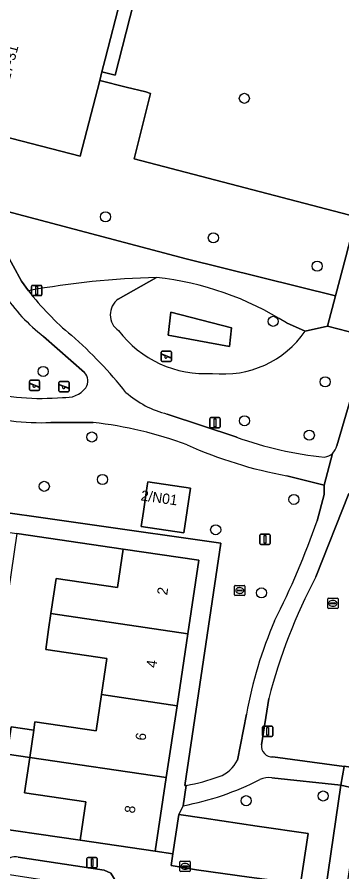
# Model space of a CAD drawing. Extents: x 163683 to 164494, y 382709 to 383872.
# Drawn here: x 164137.6 to 164169, y 383039.4 to 383122.3 of the extents above; entities that cross this region are included whole.
import ezdxf

# ---------------------------------------------------------------- set-up
doc = ezdxf.new("R2010")
doc.units = 0
for name, color, linetype in [('IMGEO_Boom', 7, 'Continuous'), ('IMGEO_Erf', 7, 'Continuous'), ('IMGEO_Groenvoorziening', 7, 'Continuous'), ('IMGEO_Kolk', 7, 'Continuous'), ('IMGEO_Lichtmast', 7, 'Continuous'), ('IMGEO_Pand', 7, 'Continuous'), ('IMGEO_Pand_nummerreeks', 7, 'Continuous'), ('IMGEO_Parkeervlak_open', 7, 'Continuous'), ('IMGEO_Rioolput', 7, 'Continuous'), ('IMGEO_Speelvoorziening', 7, 'Continuous'), ('IMGEO_Voetpad_halfverhard', 7, 'Continuous'), ('IMGEO_Voetpad_open', 7, 'Continuous')]:
    doc.layers.add(name, color=color, linetype=linetype)

msp = doc.modelspace()

# ---------------------------------------------------------------- linework, layer by layer
at = {"layer": 'IMGEO_Boom'}
for centre in [(164159.549, 383114.408), (164146.112, 383102.917), (164156.55, 383100.879), (164166.599, 383098.137), (164162.334, 383092.784), (164140.074, 383087.929), (164167.374, 383086.924), (164159.567, 383083.143), (164144.782, 383081.568), (164165.84, 383081.743), (164145.822, 383077.443), (164140.182, 383076.784), (164164.349, 383075.518), (164156.775, 383072.577), (164161.207, 383066.45), (164159.731, 383046.3), (164167.183, 383046.756)]:
    msp.add_circle(centre, 0.489, dxfattribs=at)
at = {"layer": 'IMGEO_Erf'}
msp.add_lwpolyline([(164146.251, 383060.095), (164140.317, 383060.973), (164140.602, 383062.903), (164140.829, 383064.44), (164141.333, 383067.849), (164147.268, 383066.971), (164147.817, 383070.691), (164137.509, 383072.212), (164133.407, 383043.974), (164143.649, 383042.486), (164144.194, 383046.176), (164138.26, 383047.054), (164138.767, 383050.485), (164136.597, 383050.805), (164136.989, 383053.462), (164139.16, 383053.142), (164139.279, 383053.95), (164145.213, 383053.072), (164145.733, 383056.587)], close=True, dxfattribs=at)
at = {"layer": 'IMGEO_Groenvoorziening'}
for points in [[(164176.537, 383126.569), (164154.315, 383132.306), (164153.975, 383138.872), (164152.776, 383139.237), (164150.9, 383131.848), (164147.04, 383116.646), (164145.764, 383116.973), (164145.551, 383116.143), (164148.108, 383115.477), (164150.025, 383115.042), (164150.47, 383114.883), (164148.895, 383108.547), (164170.385, 383102.927)], [(164130.601, 383105.021), (164153.924, 383098.841), (164168.382, 383095.258), (164169.377, 383099.053), (164170.385, 383102.927), (164148.895, 383108.547), (164150.47, 383114.883), (164150.025, 383115.042), (164148.108, 383115.477), (164145.551, 383116.143), (164143.667, 383108.811), (164132.278, 383111.736)], [(164158.309, 383092.167), (164152.448, 383093.678), (164152.161, 383091.446), (164158.123, 383090.334)], [(164158.123, 383090.334), (164152.161, 383091.446), (164152.448, 383093.678), (164158.309, 383092.167)], [(164149.789, 383074.346), (164150.153, 383076.819), (164150.211, 383077.209), (164154.321, 383076.602), (164153.683, 383072.277), (164149.573, 383072.884)]]:
    msp.add_lwpolyline(points, close=True, dxfattribs=at)
for points in [[(164163.632, 383092.626), (164165.451, 383091.845), (164167.61, 383092.316), (164168.382, 383095.258), (164153.924, 383098.841), (164130.601, 383105.021), (164130.639, 383104.838), (164133.407, 383104.018)], [(164135.521, 383101.151), (164137.968, 383096.684), (164138.654, 383095.757)], [(164151.054, 383097.04), (164147.334, 383094.937)], [(164147.334, 383094.937), (164151.054, 383097.04)], [(164165.451, 383091.845), (164163.632, 383092.626)], [(164168.497, 383080.71), (164171.615, 383091.268), (164167.61, 383092.316), (164165.451, 383091.845)], [(164144.086, 383087.825), (164140.116, 383091.323)], [(164152.091, 383083.795), (164158.807, 383081.554)], [(164144.917, 383082.973), (164140.824, 383082.983)], [(164132.4, 383077.957), (164131.864, 383074.9), (164157.283, 383071.277), (164153.793, 383047.768), (164153.917, 383047.788)], [(164167.263, 383076.913), (164163.67, 383077.798)], [(164166.586, 383073.45), (164167.273, 383076.003), (164167.263, 383076.913)], [(164169.676, 383076.099), (164166.477, 383067.998)], [(164161.918, 383056.219), (164161.209, 383051.719)], [(164158.873, 383050.234), (164159.754, 383054.687)], [(164162.319, 383050.556), (164169.216, 383049.609), (164169.223, 383049.653), (164170.675, 383049.429), (164171.064, 383051.879), (164171.559, 383055)], [(164153.629, 383045.816), (164153.2, 383044.955), (164155.662, 383044.603), (164160.791, 383043.822), (164165.739, 383043.108), (164164.98, 383038.234), (164167.449, 383037.807), (164168.897, 383047.801), (164162.226, 383048.525)]]:
    msp.add_lwpolyline(points, dxfattribs=at)
for centre, radius, start, end in [((164153.179, 383015.942), 81.126, 91.50073, 100.31376), ((164153.179, 383015.942), 81.126, 91.50073, 100.31376), ((164147.804, 383067.65), 29.57, 57.63606, 83.68891), ((164147.804, 383067.65), 29.57, 57.63606, 83.68891), ((164159.128, 383111.286), 25.697, 217.1799, 230.57615), ((164150.163, 383104.484), 16.558, 212.9844, 232.6429), ((164148.439, 383093.423), 1.874, 126.13062, 235.10876), ((164148.439, 383093.423), 1.874, 126.13062, 235.10876), ((164155.738, 383098.19), 10.48, 216.98172, 273.91583), ((164155.738, 383098.19), 10.48, 216.98172, 273.91583), ((164157.528, 383097.287), 9.612, 263.58564, 325.518), ((164157.528, 383097.287), 9.612, 263.58564, 325.518), ((164114.666, 383059.327), 42.697, 38.48096, 48.76649), ((164143.179, 383087), 1.227, 327.06643, 42.28285), ((164139.889, 383108.442), 23.13, 255.39685, 275.11791), ((164142.228, 383087.939), 2.55, 263.79675, 320.96607), ((164154.385, 383093.027), 9.513, 228.56764, 256.0452), ((164139.731, 383105.192), 22.236, 253.05037, 272.81875), ((164140.661, 383044.977), 38.234, 69.56721, 83.60918), ((164171.601, 383120.302), 43.238, 245.9918, 259.43054), ((164170.806, 383114.682), 35.235, 250.08908, 264.31636), ((164167.139, 383080.996), 1.386, 277.38337, 312.76546), ((164167.13, 383081.004), 1.399, 312.80443, 347.85765), ((164092.514, 383099.049), 78.371, 333.21214, 340.9352), ((164213.759, 383042.926), 53.518, 152.06448, 165.61819), ((164200.877, 383047.245), 41.791, 156.77014, 169.74186), ((164162.233, 383051.585), 1.033, 172.54823, 274.7803), ((164156.069, 383051.569), 3.106, 289.52971, 334.53785), ((164150.848, 383065.636), 18.11, 279.75605, 290.21855), ((164162.012, 383045.902), 2.632, 85.34553, 111.59273), ((164148.762, 383072.184), 26.814, 280.45862, 297.26222)]:
    msp.add_arc(centre, radius, start, end, dxfattribs=at)
at = {"layer": 'IMGEO_Kolk'}
for p, q in [((164153.312, 383039.503), (164153.312, 383040.355)), ((164153.387, 383040.429), (164154.239, 383040.429)), ((164153.8, 383040.209), (164153.825, 383040.209)), ((164154.313, 383040.355), (164154.313, 383039.503)), ((164154.239, 383039.429), (164153.387, 383039.429)), ((164153.571, 383039.923), (164153.571, 383039.935)), ((164154.009, 383039.886), (164153.611, 383039.886)), ((164153.614, 383039.972), (164154.012, 383039.972)), ((164153.823, 383039.649), (164153.798, 383039.649)), ((164154.055, 383039.935), (164154.055, 383039.923))]:
    msp.add_line(p, q, dxfattribs=at)
for points in [[(164153.312, 383039.503), (164153.312, 383040.355)], [(164153.387, 383040.429), (164154.239, 383040.429)], [(164154.313, 383040.355), (164154.313, 383039.503)], [(164154.239, 383039.429), (164153.387, 383039.429)]]:
    msp.add_lwpolyline(points, dxfattribs=at)
for centre, radius, start, end in [((164153.389, 383040.353), 0.0765, 91.55205, 178.44795), ((164153.389, 383040.353), 0.0765, 91.55205, 178.44795), ((164154.237, 383040.353), 0.0765, 1.55205, 88.44795), ((164154.237, 383040.353), 0.0765, 1.55205, 88.44795), ((164153.389, 383039.505), 0.0765, 181.55205, 268.44795), ((164153.389, 383039.505), 0.0765, 181.55205, 268.44795), ((164153.611, 383039.932), 0.0403, 85.87752, 175.75265), ((164153.608, 383039.922), 0.0366, 178.93798, 274.71019), ((164154.012, 383039.929), 0.043, 264.86636, 352.45326), ((164154.016, 383039.934), 0.0386, 1.73085, 96.63898), ((164154.237, 383039.505), 0.0765, 271.55205, 358.44795), ((164154.237, 383039.505), 0.0765, 271.55205, 358.44795)]:
    msp.add_arc(centre, radius, start, end, dxfattribs=at)
for centre, major_axis, ratio, start_param, end_param in [((164153.799, 383039.929), (-0.387, 0.002), 0.722429, 4.712389, 7.853982), ((164153.824, 383039.929), (-0.39, 0.002), 0.717154, 1.570796, 4.712389)]:
    msp.add_ellipse(centre, major_axis=major_axis, ratio=ratio, start_param=start_param, end_param=end_param, dxfattribs=at)
at = {"layer": 'IMGEO_Lichtmast'}
for p, q in [((164138.958, 383095.375), (164138.958, 383096.175)), ((164138.958, 383096.175), (164138.958, 383095.375)), ((164139.058, 383096.275), (164139.848, 383096.275)), ((164139.848, 383096.275), (164139.058, 383096.275)), ((164139.948, 383096.175), (164139.948, 383095.375)), ((164139.948, 383095.375), (164139.948, 383096.175)), ((164139.848, 383095.275), (164139.058, 383095.275)), ((164139.058, 383095.275), (164139.848, 383095.275)), ((164156.212, 383082.545), (164156.212, 383083.345)), ((164156.212, 383083.345), (164156.212, 383082.545)), ((164156.312, 383083.445), (164157.102, 383083.445)), ((164157.102, 383083.445), (164156.312, 383083.445)), ((164157.202, 383083.345), (164157.202, 383082.545)), ((164157.202, 383082.545), (164157.202, 383083.345)), ((164157.102, 383082.445), (164156.312, 383082.445)), ((164156.312, 383082.445), (164157.102, 383082.445)), ((164161.051, 383071.246), (164161.051, 383072.046)), ((164161.051, 383072.046), (164161.051, 383071.246)), ((164161.151, 383072.146), (164161.941, 383072.146)), ((164161.941, 383072.146), (164161.151, 383072.146)), ((164162.041, 383072.046), (164162.041, 383071.246)), ((164162.041, 383071.246), (164162.041, 383072.046)), ((164161.941, 383071.146), (164161.151, 383071.146)), ((164161.151, 383071.146), (164161.941, 383071.146)), ((164161.307, 383052.633), (164161.307, 383053.433)), ((164161.307, 383053.433), (164161.307, 383052.633)), ((164161.407, 383053.533), (164162.197, 383053.533)), ((164162.197, 383053.533), (164161.407, 383053.533)), ((164162.297, 383053.433), (164162.297, 383052.633)), ((164162.297, 383052.633), (164162.297, 383053.433)), ((164162.197, 383052.533), (164161.407, 383052.533)), ((164161.407, 383052.533), (164162.197, 383052.533)), ((164144.316, 383039.879), (164144.316, 383040.679)), ((164144.316, 383040.679), (164144.316, 383039.879)), ((164144.416, 383040.779), (164145.206, 383040.779)), ((164145.206, 383040.779), (164144.416, 383040.779)), ((164145.306, 383040.679), (164145.306, 383039.879)), ((164145.306, 383039.879), (164145.306, 383040.679)), ((164145.206, 383039.779), (164144.416, 383039.779)), ((164144.416, 383039.779), (164145.206, 383039.779))]:
    msp.add_line(p, q, dxfattribs=at)
for points in [[(164139.378, 383096.15), (164139.528, 383096.15), (164139.528, 383095.4), (164139.378, 383095.4), (164139.378, 383096.15)], [(164156.632, 383083.32), (164156.782, 383083.32), (164156.782, 383082.57), (164156.632, 383082.57), (164156.632, 383083.32)], [(164161.471, 383072.021), (164161.621, 383072.021), (164161.621, 383071.271), (164161.471, 383071.271), (164161.471, 383072.021)], [(164161.727, 383053.408), (164161.877, 383053.408), (164161.877, 383052.658), (164161.727, 383052.658), (164161.727, 383053.408)], [(164144.736, 383040.654), (164144.886, 383040.654), (164144.886, 383039.904), (164144.736, 383039.904), (164144.736, 383040.654)]]:
    msp.add_lwpolyline(points, dxfattribs=at)
for centre, start, end in [((164139.058, 383096.175), 90, 180), ((164139.058, 383096.175), 90, 180), ((164139.848, 383096.175), 0, 90), ((164139.848, 383096.175), 360, 90), ((164139.058, 383095.375), 180, 270), ((164139.058, 383095.375), 180, 270), ((164139.848, 383095.375), 270, 0), ((164139.848, 383095.375), 270, 0), ((164156.312, 383083.345), 90, 180), ((164156.312, 383083.345), 90, 180), ((164157.102, 383083.345), 0, 90), ((164157.102, 383083.345), 360, 90), ((164156.312, 383082.545), 180, 270), ((164156.312, 383082.545), 180, 270), ((164157.102, 383082.545), 270, 0), ((164157.102, 383082.545), 270, 0), ((164161.151, 383072.046), 90, 180), ((164161.151, 383072.046), 90, 180), ((164161.941, 383072.046), 0, 90), ((164161.941, 383072.046), 360, 90), ((164161.151, 383071.246), 180, 270), ((164161.151, 383071.246), 180, 270), ((164161.941, 383071.246), 270, 0), ((164161.941, 383071.246), 270, 0), ((164161.407, 383053.433), 90, 180), ((164161.407, 383053.433), 90, 180), ((164162.197, 383053.433), 0, 90), ((164162.197, 383053.433), 360, 90), ((164161.407, 383052.633), 180, 270), ((164161.407, 383052.633), 180, 270), ((164162.197, 383052.633), 270, 0), ((164162.197, 383052.633), 270, 0), ((164144.416, 383040.679), 90, 180), ((164144.416, 383040.679), 90, 180), ((164145.206, 383040.679), 0, 90), ((164145.206, 383040.679), 360, 90), ((164144.416, 383039.879), 180, 270), ((164144.416, 383039.879), 180, 270), ((164145.206, 383039.879), 270, 0), ((164145.206, 383039.879), 270, 0)]:
    msp.add_arc(centre, 0.1, start, end, dxfattribs=at)
at = {"layer": 'IMGEO_Pand'}
for points in [[(164146.083, 383118.215), (164147.597, 383124.11), (164136.228, 383127.03), (164134.658, 383120.919), (164134.287, 383121.015), (164133.546, 383118.131), (164133.897, 383118.041), (164132.278, 383111.736), (164143.667, 383108.811), (164145.551, 383116.143), (164145.764, 383116.973)], [(164149.789, 383074.346), (164149.573, 383072.884), (164153.683, 383072.277), (164154.321, 383076.602), (164150.211, 383077.209), (164150.153, 383076.819)], [(164140.829, 383064.44), (164154.072, 383062.486), (164155.134, 383069.618), (164147.817, 383070.691), (164147.268, 383066.971), (164141.333, 383067.849)], [(164140.829, 383064.44), (164140.602, 383062.903), (164140.317, 383060.973), (164146.251, 383060.095), (164145.733, 383056.587), (164153.034, 383055.509), (164154.072, 383062.486)], [(164153.034, 383055.509), (164145.733, 383056.587), (164145.213, 383053.072), (164139.279, 383053.95), (164139.16, 383053.142), (164138.767, 383050.485), (164151.995, 383048.533)], [(164139.16, 383053.142), (164136.989, 383053.462), (164136.597, 383050.805), (164138.767, 383050.485)], [(164151.995, 383048.533), (164138.767, 383050.485), (164138.26, 383047.054), (164144.194, 383046.176), (164143.649, 383042.486), (164150.932, 383041.393)]]:
    msp.add_lwpolyline(points, close=True, dxfattribs=at)
at = {"layer": 'IMGEO_Parkeervlak_open'}
msp.add_lwpolyline([(164165.739, 383043.108), (164160.791, 383043.822), (164155.662, 383044.603), (164153.2, 383044.955), (164152.624, 383041.139), (164152.452, 383039.999), (164154.923, 383039.607), (164160.032, 383038.872), (164164.98, 383038.234)], close=True, dxfattribs=at)
msp.add_lwpolyline([(164136.586, 383040.572), (164135.774, 383039.862), (164134.563, 383039.466), (164135.307, 383039.353), (164148.16, 383037.399), (164147.229, 383038.285), (164146.622, 383039.274), (164145.976, 383039.564), (164137.638, 383040.839)], dxfattribs=at)
msp.add_arc((164137.385, 383039.628), 1.237, 78.21996, 130.26224, dxfattribs=at)
at = {"layer": 'IMGEO_Rioolput'}
for p, q in [((164158.598, 383066.256), (164158.598, 383067.108)), ((164158.673, 383067.182), (164159.525, 383067.182)), ((164158.857, 383066.676), (164158.857, 383066.688)), ((164158.9, 383066.725), (164159.298, 383066.725)), ((164159.086, 383066.962), (164159.111, 383066.962)), ((164159.341, 383066.688), (164159.341, 383066.676)), ((164159.599, 383067.108), (164159.599, 383066.256)), ((164159.525, 383066.182), (164158.673, 383066.182)), ((164159.295, 383066.639), (164158.897, 383066.639)), ((164159.109, 383066.402), (164159.084, 383066.402)), ((164167.625, 383065.009), (164167.625, 383065.861)), ((164167.7, 383065.935), (164168.552, 383065.935)), ((164168.626, 383065.861), (164168.626, 383065.009)), ((164167.884, 383065.429), (164167.884, 383065.441)), ((164168.322, 383065.392), (164167.924, 383065.392)), ((164167.927, 383065.478), (164168.325, 383065.478)), ((164168.136, 383065.155), (164168.111, 383065.155)), ((164168.113, 383065.715), (164168.138, 383065.715)), ((164168.368, 383065.441), (164168.368, 383065.429)), ((164168.552, 383064.935), (164167.7, 383064.935))]:
    msp.add_line(p, q, dxfattribs=at)
for points in [[(164158.598, 383066.256), (164158.598, 383067.108)], [(164158.673, 383067.182), (164159.525, 383067.182)], [(164159.599, 383067.108), (164159.599, 383066.256)], [(164159.525, 383066.182), (164158.673, 383066.182)], [(164167.625, 383065.009), (164167.625, 383065.861)], [(164167.7, 383065.935), (164168.552, 383065.935)], [(164168.626, 383065.861), (164168.626, 383065.009)], [(164168.552, 383064.935), (164167.7, 383064.935)]]:
    msp.add_lwpolyline(points, dxfattribs=at)
for centre, radius, start, end in [((164158.675, 383067.106), 0.0765, 91.55205, 178.44795), ((164158.675, 383067.106), 0.0765, 91.55205, 178.44795), ((164158.897, 383066.685), 0.0403, 85.87752, 175.75265), ((164159.302, 383066.687), 0.0386, 1.73085, 96.63898), ((164159.523, 383067.106), 0.0765, 1.55205, 88.44795), ((164159.523, 383067.106), 0.0765, 1.55205, 88.44795), ((164158.675, 383066.258), 0.0765, 181.55205, 268.44795), ((164158.675, 383066.258), 0.0765, 181.55205, 268.44795), ((164158.894, 383066.675), 0.0366, 178.93798, 274.71019), ((164159.298, 383066.682), 0.043, 264.86636, 352.45326), ((164159.523, 383066.258), 0.0765, 271.55205, 358.44795), ((164159.523, 383066.258), 0.0765, 271.55205, 358.44795), ((164167.702, 383065.859), 0.0765, 91.55205, 178.44795), ((164167.702, 383065.859), 0.0765, 91.55205, 178.44795), ((164168.55, 383065.859), 0.0765, 1.55205, 88.44795), ((164168.55, 383065.859), 0.0765, 1.55205, 88.44795), ((164167.924, 383065.438), 0.0403, 85.87752, 175.75265), ((164167.921, 383065.428), 0.0366, 178.93798, 274.71019), ((164168.325, 383065.435), 0.043, 264.86636, 352.45326), ((164168.329, 383065.44), 0.0386, 1.73085, 96.63898), ((164167.702, 383065.011), 0.0765, 181.55205, 268.44795), ((164167.702, 383065.011), 0.0765, 181.55205, 268.44795), ((164168.55, 383065.011), 0.0765, 271.55205, 358.44795), ((164168.55, 383065.011), 0.0765, 271.55205, 358.44795)]:
    msp.add_arc(centre, radius, start, end, dxfattribs=at)
for centre, major_axis, ratio, start_param, end_param in [((164159.085, 383066.682), (-0.387, 0.002), 0.722429, 4.712389, 7.853982), ((164159.11, 383066.682), (-0.39, 0.002), 0.717154, 1.570796, 4.712389), ((164168.112, 383065.435), (-0.387, 0.002), 0.722429, 4.712389, 7.853982), ((164168.137, 383065.435), (-0.39, 0.002), 0.717154, 1.570796, 4.712389)]:
    msp.add_ellipse(centre, major_axis=major_axis, ratio=ratio, start_param=start_param, end_param=end_param, dxfattribs=at)
at = {"layer": 'IMGEO_Speelvoorziening'}
for p, q in [((164151.597, 383089.895), (164152.387, 383089.895)), ((164152.387, 383089.895), (164151.597, 383089.895)), ((164151.497, 383088.995), (164151.497, 383089.795)), ((164151.497, 383089.795), (164151.497, 383088.995)), ((164151.88, 383089.423), (164151.541, 383089.56)), ((164151.566, 383089.62), (164152.442, 383089.267)), ((164152.418, 383089.207), (164152.078, 383089.344)), ((164152.487, 383089.795), (164152.487, 383088.995)), ((164152.487, 383088.995), (164152.487, 383089.795)), ((164152.387, 383088.895), (164151.597, 383088.895)), ((164151.597, 383088.895), (164152.387, 383088.895)), ((164138.742, 383086.166), (164138.742, 383086.966)), ((164138.742, 383086.966), (164138.742, 383086.166)), ((164139.125, 383086.594), (164138.786, 383086.731)), ((164138.811, 383086.791), (164139.687, 383086.438)), ((164138.842, 383087.066), (164139.632, 383087.066)), ((164139.632, 383087.066), (164138.842, 383087.066)), ((164139.732, 383086.966), (164139.732, 383086.166)), ((164139.732, 383086.166), (164139.732, 383086.966)), ((164141.6, 383086.048), (164141.6, 383086.848)), ((164141.6, 383086.848), (164141.6, 383086.048)), ((164141.983, 383086.476), (164141.644, 383086.613)), ((164141.669, 383086.673), (164142.545, 383086.32)), ((164141.7, 383086.948), (164142.49, 383086.948)), ((164142.49, 383086.948), (164141.7, 383086.948)), ((164142.59, 383086.848), (164142.59, 383086.048)), ((164142.59, 383086.048), (164142.59, 383086.848)), ((164139.632, 383086.066), (164138.842, 383086.066)), ((164138.842, 383086.066), (164139.632, 383086.066)), ((164139.663, 383086.378), (164139.323, 383086.515)), ((164142.49, 383085.948), (164141.7, 383085.948)), ((164141.7, 383085.948), (164142.49, 383085.948)), ((164142.521, 383086.26), (164142.181, 383086.397))]:
    msp.add_line(p, q, dxfattribs=at)
for centre, radius, start, end in [((164151.597, 383089.795), 0.1, 90, 180), ((164151.597, 383089.795), 0.1, 90, 180), ((164152.387, 383089.795), 0.1, 0, 90), ((164152.387, 383089.795), 0.1, 360, 90), ((164151.554, 383089.59), 0.0327, 68.07798, 248.07798), ((164151.959, 383089.333), 0.12, 130.99278, 5.16318), ((164152.43, 383089.237), 0.0327, 248.07798, 68.07798), ((164151.597, 383088.995), 0.1, 180, 270), ((164151.597, 383088.995), 0.1, 180, 270), ((164152.387, 383088.995), 0.1, 270, 0), ((164152.387, 383088.995), 0.1, 270, 0), ((164138.842, 383086.966), 0.1, 90, 180), ((164138.842, 383086.966), 0.1, 90, 180), ((164138.799, 383086.761), 0.0327, 68.07798, 248.07798), ((164139.204, 383086.504), 0.12, 130.99278, 5.16318), ((164139.632, 383086.966), 0.1, 0, 90), ((164139.632, 383086.966), 0.1, 360, 90), ((164141.7, 383086.848), 0.1, 90, 180), ((164141.7, 383086.848), 0.1, 90, 180), ((164141.657, 383086.643), 0.0327, 68.07798, 248.07798), ((164142.49, 383086.848), 0.1, 0, 90), ((164142.49, 383086.848), 0.1, 360, 90), ((164138.842, 383086.166), 0.1, 180, 270), ((164138.842, 383086.166), 0.1, 180, 270), ((164139.632, 383086.166), 0.1, 270, 0), ((164139.632, 383086.166), 0.1, 270, 0), ((164139.675, 383086.408), 0.0327, 248.07798, 68.07798), ((164141.7, 383086.048), 0.1, 180, 270), ((164141.7, 383086.048), 0.1, 180, 270), ((164142.062, 383086.386), 0.12, 130.99278, 5.16318), ((164142.49, 383086.048), 0.1, 270, 0), ((164142.49, 383086.048), 0.1, 270, 0), ((164142.533, 383086.29), 0.0327, 248.07798, 68.07798)]:
    msp.add_arc(centre, radius, start, end, dxfattribs=at)
at = {"layer": 'IMGEO_Voetpad_halfverhard'}
for points in [[(164138.654, 383095.757), (164137.968, 383096.684), (164135.521, 383101.151)], [(164140.116, 383091.323), (164144.086, 383087.825)], [(164171.016, 383082.356), (164173.426, 383090.794), (164171.615, 383091.268), (164168.497, 383080.71)], [(164158.807, 383081.554), (164152.091, 383083.795)], [(164140.824, 383082.983), (164144.917, 383082.973)], [(164163.67, 383077.798), (164167.263, 383076.913), (164168.08, 383079.978)], [(164168.08, 383079.978), (164167.263, 383076.913), (164167.273, 383076.003), (164166.586, 383073.45)], [(164166.477, 383067.998), (164169.676, 383076.099)], [(164161.209, 383051.719), (164161.918, 383056.219)], [(164159.754, 383054.687), (164158.873, 383050.234)], [(164162.226, 383048.525), (164168.897, 383047.801), (164169.216, 383049.609), (164162.319, 383050.556)], [(164153.917, 383047.788), (164153.629, 383045.816)]]:
    msp.add_lwpolyline(points, dxfattribs=at)
for centre, radius, start, end in [((164159.128, 383111.286), 25.697, 217.1799, 230.57615), ((164150.163, 383104.484), 16.558, 212.9844, 232.6429), ((164114.666, 383059.327), 42.697, 38.48096, 48.76649), ((164143.179, 383087), 1.227, 327.06643, 42.28285), ((164139.889, 383108.442), 23.13, 255.39685, 275.11791), ((164142.228, 383087.939), 2.55, 263.79675, 320.96607), ((164154.385, 383093.027), 9.513, 228.56764, 256.0452), ((164139.731, 383105.192), 22.236, 253.05037, 272.81875), ((164140.661, 383044.977), 38.234, 69.56721, 83.60918), ((164171.601, 383120.302), 43.238, 245.9918, 259.43054), ((164170.806, 383114.682), 35.235, 250.08908, 264.31636), ((164167.139, 383080.996), 1.386, 277.38337, 312.76546), ((164167.13, 383081.004), 1.399, 312.80443, 347.85765), ((164092.514, 383099.049), 78.371, 333.21214, 340.9352), ((164213.759, 383042.926), 53.518, 152.06448, 165.61819), ((164200.877, 383047.245), 41.791, 156.77014, 169.74186), ((164162.233, 383051.585), 1.033, 172.54823, 274.7803), ((164156.069, 383051.569), 3.106, 289.52971, 334.53785), ((164150.848, 383065.636), 18.11, 279.75605, 290.21855), ((164162.012, 383045.902), 2.632, 85.34553, 111.59273), ((164148.762, 383072.184), 26.814, 280.45862, 297.26222)]:
    msp.add_arc(centre, radius, start, end, dxfattribs=at)
at = {"layer": 'IMGEO_Voetpad_open'}
for points in [[(164150.9, 383131.848), (164149.674, 383132.195), (164149.112, 383130.005), (164147.597, 383124.11), (164146.083, 383118.215), (164145.764, 383116.973), (164147.04, 383116.646)], [(164170.738, 383049.419), (164170.675, 383049.429), (164169.223, 383049.653), (164169.216, 383049.609), (164168.897, 383047.801), (164170.868, 383047.353), (164178.286, 383046.267), (164187.643, 383044.904), (164191.089, 383044.406), (164192.969, 383044.135), (164196.589, 383043.612), (164205.444, 383042.29), (164212.862, 383041.205), (164216.861, 383040.694), (164217.162, 383042.632)]]:
    msp.add_lwpolyline(points, close=True, dxfattribs=at)
for points in [[(164179.925, 383127.281), (164176.537, 383126.569), (164170.385, 383102.927), (164169.377, 383099.053), (164168.382, 383095.258), (164167.61, 383092.316), (164171.615, 383091.268), (164173.426, 383090.794), (164178.183, 383089.55), (164179.441, 383091.761)], [(164116.288, 383075.423), (164118.425, 383075.085), (164125.764, 383073.946), (164135.965, 383072.44), (164137.509, 383072.212), (164147.817, 383070.691), (164155.134, 383069.618), (164154.072, 383062.486), (164153.034, 383055.509), (164151.995, 383048.533), (164150.932, 383041.393), (164152.624, 383041.139), (164153.2, 383044.955), (164153.629, 383045.816), (164153.917, 383047.788), (164153.793, 383047.768), (164157.283, 383071.277), (164131.864, 383074.9)], [(164163.661, 383030.372), (164168.232, 383029.342), (164169.088, 383035.191), (164169.96, 383041.146), (164170.868, 383047.353), (164168.897, 383047.801), (164167.449, 383037.807), (164164.98, 383038.234), (164160.032, 383038.872), (164154.923, 383039.607), (164152.452, 383039.999), (164152.624, 383041.139), (164150.932, 383041.393), (164143.649, 383042.486)], [(164143.649, 383042.486), (164133.407, 383043.974), (164131.862, 383044.198), (164121.476, 383045.707), (164114.215, 383046.807), (164112.228, 383046.662), (164112.133, 383046.029), (164108.792, 383046.581), (164104.627, 383047.219), (164104.492, 383044.036), (164106.672, 383043.705), (164106.745, 383044.193), (164112.941, 383043.254), (164112.868, 383042.763), (164113.99, 383042.593)], [(164137.638, 383040.839), (164145.976, 383039.564), (164146.622, 383039.274), (164147.229, 383038.285), (164148.16, 383037.399), (164149.698, 383037.199), (164150.489, 383037.071), (164150.71, 383038.043), (164153.167, 383037.656), (164155.404, 383037.158)]]:
    msp.add_lwpolyline(points, dxfattribs=at)
msp.add_arc((164137.385, 383039.628), 1.237, 78.21996, 130.26224, dxfattribs=at)

# ---------------------------------------------------------------- texts
at = {"layer": 'IMGEO_Pand_nummerreeks'}
for s, rotation, p in [('17-31', 75.48719, (164136.833, 383116.133)), ('2/N01', 351.99259, (164149.475, 383075.427)), ('2', 81.53228, (164152.075, 383066.186)), ('4', 81.53228, (164151.025, 383059.132)), ('6', 81.53189, (164149.974, 383052.076)), ('8', 81.53228, (164148.924, 383045.023))]:
    msp.add_text(s, height=1, rotation=rotation, dxfattribs=at).set_placement(p)

doc.saveas('drawing.dxf')
